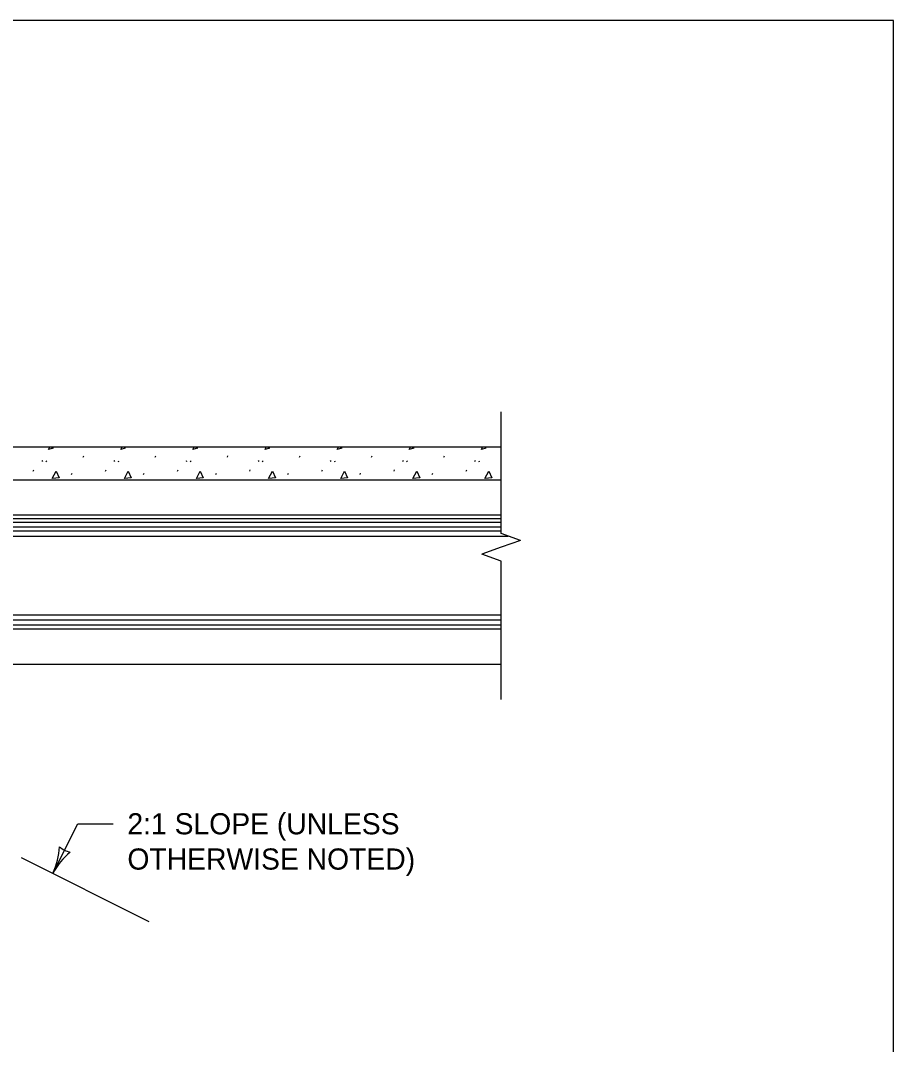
# Model space of a CAD drawing. Extents: x 49991.4 to 50021, y 49987.6 to 50011.4.
# Drawn here: x 50006.14 to 50008.615, y 50008.359 to 50011.263 of the extents above; entities that cross this region are included whole.
import ezdxf

# ---------------------------------------------------------------- set-up
doc = ezdxf.new("R2010")
doc.units = 0
for name, color, linetype in [('Level 1', 7, 'Continuous'), ('Level 2', 7, 'Continuous'), ('Level 3', 7, 'Continuous'), ('Level 6', 7, 'Continuous')]:
    doc.layers.add(name, color=color, linetype=linetype)

msp = doc.modelspace()

# ---------------------------------------------------------------- linework, layer by layer
at = {"layer": 'Level 1'}
for p, q in [((50004.402, 50010.0536), (50007.502, 50010.0536)), ((50006.3173, 50010.025), (50006.3189, 50010.0286)), ((50006.5218, 50010.025), (50006.5234, 50010.0286)), ((50006.7263, 50010.025), (50006.7279, 50010.0286)), ((50006.9307, 50010.025), (50006.9324, 50010.0286)), ((50007.1352, 50010.025), (50007.1368, 50010.0286)), ((50007.3397, 50010.025), (50007.3413, 50010.0286)), ((50006.2001, 50010.015), (50006.2017, 50010.0125)), ((50006.2117, 50010.0141), (50006.2133, 50010.0116)), ((50006.4046, 50010.015), (50006.4062, 50010.0125)), ((50006.4162, 50010.0141), (50006.4178, 50010.0116)), ((50006.6091, 50010.015), (50006.6107, 50010.0125)), ((50006.6207, 50010.0141), (50006.6223, 50010.0116)), ((50006.8135, 50010.015), (50006.8152, 50010.0125)), ((50006.8252, 50010.0141), (50006.8268, 50010.0116)), ((50007.018, 50010.015), (50007.0197, 50010.0125)), ((50007.0297, 50010.0141), (50007.0313, 50010.0116)), ((50007.2225, 50010.015), (50007.2241, 50010.0125)), ((50007.2341, 50010.0141), (50007.2358, 50010.0116)), ((50007.427, 50010.015), (50007.4286, 50010.0125)), ((50007.4386, 50010.0141), (50007.4402, 50010.0116)), ((50006.1761, 50009.9849), (50006.1778, 50009.9885)), ((50006.2844, 50009.9756), (50006.286, 50009.9792)), ((50006.3806, 50009.9849), (50006.3822, 50009.9885)), ((50006.4889, 50009.9756), (50006.4905, 50009.9792)), ((50006.5851, 50009.9849), (50006.5867, 50009.9885)), ((50006.6934, 50009.9756), (50006.695, 50009.9792)), ((50006.7896, 50009.9849), (50006.7912, 50009.9885)), ((50006.8978, 50009.9756), (50006.8995, 50009.9792)), ((50006.9941, 50009.9849), (50006.9957, 50009.9885)), ((50007.1023, 50009.9756), (50007.104, 50009.9792)), ((50007.1986, 50009.9849), (50007.2002, 50009.9885)), ((50007.3068, 50009.9756), (50007.3084, 50009.9792)), ((50007.403, 50009.9849), (50007.4047, 50009.9885)), ((50004.502, 50009.9608), (50007.502, 50009.9608)), ((50004.502, 50009.8608), (50007.502, 50009.8608)), ((50004.502, 50009.8508), (50007.502, 50009.8508)), ((50004.502, 50009.8408), (50007.502, 50009.8408)), ((50004.502, 50009.8274), (50007.502, 50009.8274)), ((50004.502, 50009.8158), (50007.502, 50009.8158)), ((50004.502, 50009.8008), (50007.5225, 50009.8008)), ((50004.502, 50009.5779), (50007.502, 50009.5779)), ((50004.502, 50009.5634), (50007.502, 50009.5634)), ((50004.502, 50009.5493), (50007.502, 50009.5493)), ((50004.502, 50009.5379), (50007.502, 50009.5379)), ((50004.502, 50009.4379), (50007.502, 50009.4379)), ((50006.1413, 50008.8898), (50006.5037, 50008.7086))]:
    msp.add_line(p, q, dxfattribs=at)
msp.add_lwpolyline([(50008.6146, 50011.2628), (50000.3356, 50011.2628), (50000.3356, 50000.0624), (50008.6146, 50000.0624)], close=True, dxfattribs=at)
for points in [[(50006.2194, 50010.0461), (50006.223, 50010.0536)], [(50006.2279, 50010.0536), (50006.2324, 50010.0502), (50006.2194, 50010.0461)], [(50006.4239, 50010.0461), (50006.4275, 50010.0536)], [(50006.4324, 50010.0536), (50006.4369, 50010.0502), (50006.4239, 50010.0461)], [(50006.6284, 50010.0461), (50006.632, 50010.0536)], [(50006.6369, 50010.0536), (50006.6414, 50010.0502), (50006.6284, 50010.0461)], [(50006.8329, 50010.0461), (50006.8365, 50010.0536)], [(50006.8413, 50010.0536), (50006.8459, 50010.0502), (50006.8329, 50010.0461)], [(50007.0374, 50010.0461), (50007.041, 50010.0536)], [(50007.0458, 50010.0536), (50007.0504, 50010.0502), (50007.0374, 50010.0461)], [(50007.2419, 50010.0461), (50007.2454, 50010.0536)], [(50007.2503, 50010.0536), (50007.2548, 50010.0502), (50007.2419, 50010.0461)], [(50007.4463, 50010.0461), (50007.4499, 50010.0536)], [(50007.4548, 50010.0536), (50007.4593, 50010.0502), (50007.4463, 50010.0461)], [(50006.2296, 50009.9646), (50006.2406, 50009.9853), (50006.2491, 50009.9662), (50006.23, 50009.9646)], [(50006.4341, 50009.9646), (50006.445, 50009.9853), (50006.4536, 50009.9662), (50006.4345, 50009.9646)], [(50006.6386, 50009.9646), (50006.6495, 50009.9853), (50006.658, 50009.9662), (50006.639, 50009.9646)], [(50006.843, 50009.9646), (50006.854, 50009.9853), (50006.8625, 50009.9662), (50006.8434, 50009.9646)], [(50007.0475, 50009.9646), (50007.0585, 50009.9853), (50007.067, 50009.9662), (50007.0479, 50009.9646)], [(50007.252, 50009.9646), (50007.263, 50009.9853), (50007.2715, 50009.9662), (50007.2524, 50009.9646)], [(50007.4565, 50009.9646), (50007.4674, 50009.9853), (50007.476, 50009.9662), (50007.4569, 50009.9646)]]:
    msp.add_lwpolyline(points, dxfattribs=at)
at = {"layer": 'Level 3'}
for p, q in [((50006.2315, 50008.8447), (50006.3019, 50008.9853)), ((50006.3019, 50008.9853), (50006.4028, 50008.9853))]:
    msp.add_line(p, q, dxfattribs=at)
for centre, radius, start, end in [((50006.0183, 50008.9386), 0.233, 336.2381, 355.488), ((50006.2889, 50008.9594), 0.0548, 225.5496, 261.272), ((50006.426, 50008.7371), 0.2223, 130.8668, 151.0503)]:
    msp.add_arc(centre, radius, start, end, dxfattribs=at)
at = {"layer": 'Level 6'}
for p, q in [((50007.502, 50009.8081), (50007.502, 50010.1536)), ((50007.5568, 50009.7886), (50007.502, 50009.8081)), ((50007.5568, 50009.7886), (50007.502, 50009.7692)), ((50007.502, 50009.7692), (50007.4472, 50009.7498)), ((50007.502, 50009.7303), (50007.4472, 50009.7498)), ((50007.502, 50009.3379), (50007.502, 50009.7303))]:
    msp.add_line(p, q, dxfattribs=at)

# ---------------------------------------------------------------- texts
at = {"layer": 'Level 2'}
for s, p in [('2:1 SLOPE (UNLESS', (50006.4428, 50008.9553)), ('OTHERWISE NOTED)', (50006.4428, 50008.8553))]:
    msp.add_text(s, height=0.06, dxfattribs=at).set_placement(p)

doc.saveas('drawing.dxf')
